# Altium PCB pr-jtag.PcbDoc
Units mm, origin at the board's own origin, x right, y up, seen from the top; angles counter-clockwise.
Board outline 152.4 x 101.6 mm, 2 copper layers (Top Layer, Bottom Layer); 10 components, 21 nets, 69 pads, 6 vias.
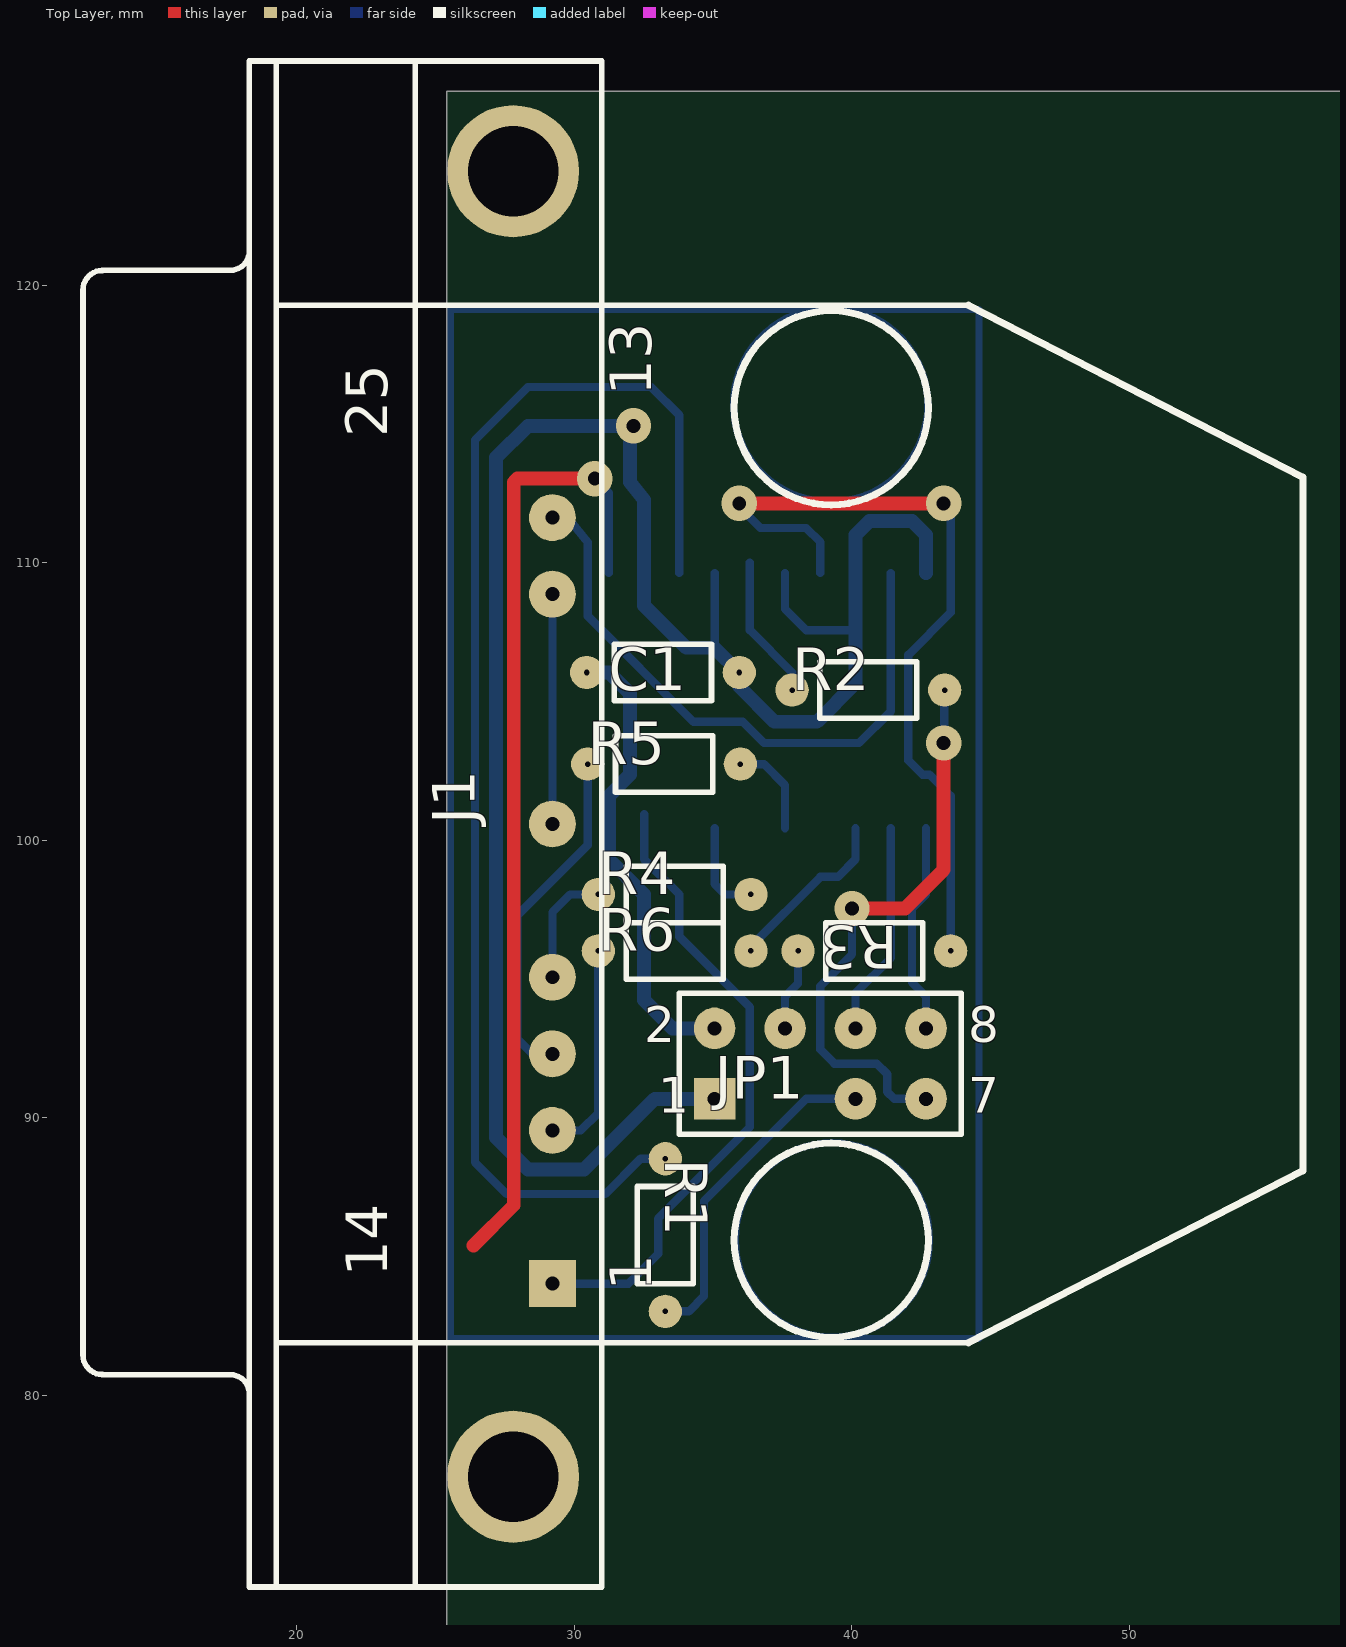
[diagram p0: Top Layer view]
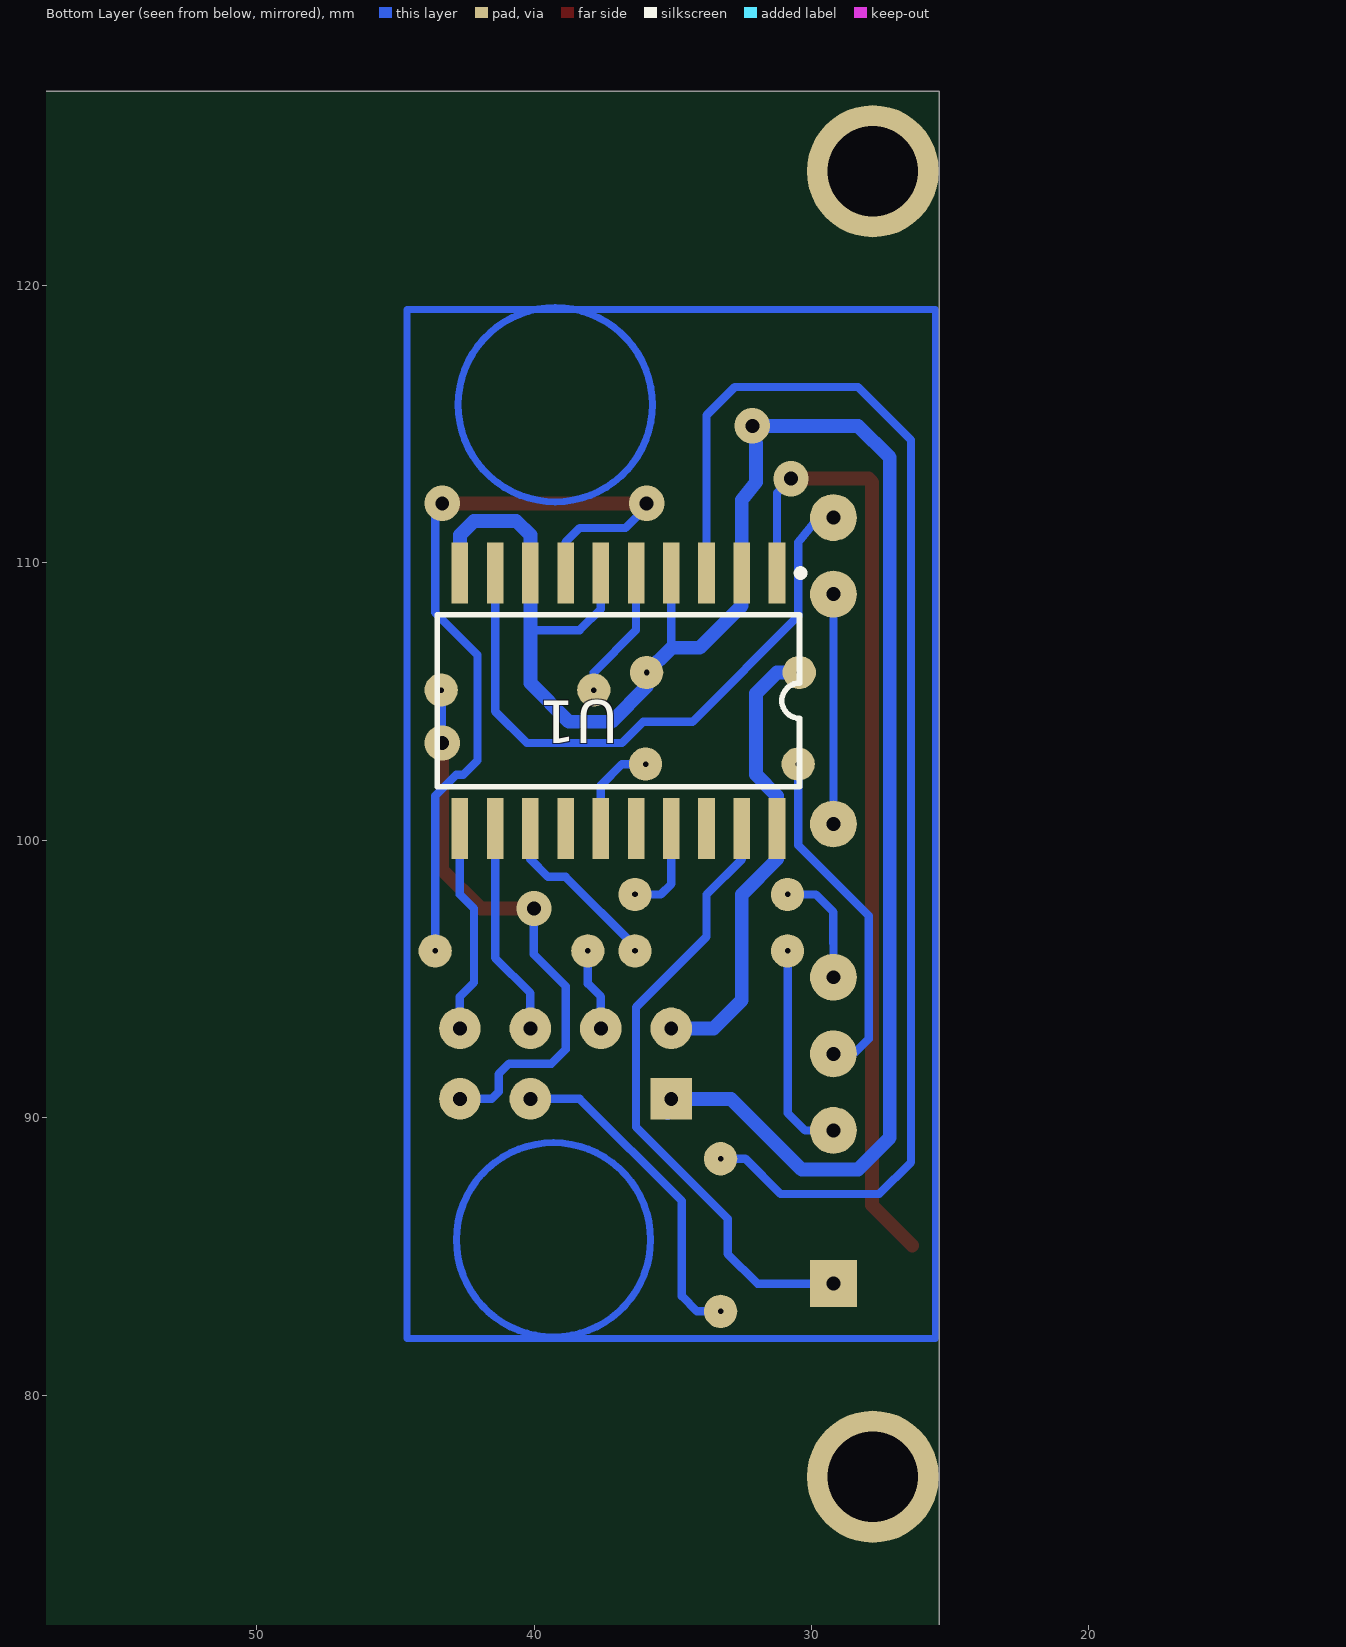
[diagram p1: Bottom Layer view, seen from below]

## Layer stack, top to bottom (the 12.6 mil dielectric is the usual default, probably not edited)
Top Layer: signal copper 0.0356
Dielectric: dielectric 0.32, FR-4, Dk 4.8
Bottom Layer: signal copper 0.0356

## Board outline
25.4,25.4 177.8,25.4 177.8,127 25.4,127

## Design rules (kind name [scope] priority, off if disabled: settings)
Clearance [All] p1: gap=0.254
ComponentClearance [All] p1: gap=0.254 collisioncheckmode=0
PolygonConnect [All] p1: connectstyle=Relief reliefconductorwidth=0.254 reliefentries=4 polygonreliefangle="90 Angle"
RoomDefinition pr-jtag [InComponentClass('pr-jtag')] p1: confinementstyle=ConfineIn formatcopy=TRUE outline 0,0 50.8,0 50.8,25.4 0,25.4
RoutingLayers [All] p1: top layer="Not Used" bottom layer=Vertical
RoutingVias [All] p1: holewidth=0.711 width=1.27 viastyle="Through Hole" minholewidth=0.711 minwidth=1.27 maxholewidth=0.711 maxwidth=1.27
SolderMaskExpansion [All] p1: expansion=0.102
TestPointUsage [All] p1: valid=0 allowmultiple=FALSE
Testpoint [All] p1: side=15 testpointundercomponent=TRUE minsize=1.016 maxsize=2.54 preferedsize=1.524 minholesize=0 maxholesize=1.016 preferedholesize=0.813 testpointgrid=0.025 style=1023 order=1234567890
Width [All] p1: maxlimit=0.5 minlimit=0.254 preferedwidth=0.5 bottomlayer_prefwidth=0.3 minimp=50.000000 maximp=50.000000 favimp=50.000000
16 further rules are at their usual default settings.

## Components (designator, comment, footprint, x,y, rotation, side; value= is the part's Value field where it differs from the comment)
C1 "Cap" "res 5mm" 35.941,106.045 r180 top (schematic designator C?)
J1 "D Connector 25" DB25-tapa 26.416,100.584 r90 top (schematic designator J?)
JP1 "Header 8" HDR2X4 35.052,90.678 r0 top (schematic designator JP?)
R1 "Res1" "Res 5mm" 33.274,88.519 r270 top (schematic designator R?)
R2 "Res1" "Res 5mm" 37.846,105.41 r0 top (schematic designator R?)
R3 "Res1" "Res 5mm" 43.561,96.012 r180 top (schematic designator R?)
R4 "Res1" "Res 5mm" 30.861,98.044 r0 top (schematic designator R?)
R5 "Res1" "Res 5mm" 30.48,102.743 r0 top (schematic designator R?)
R6 "Res1" "Res 5mm" 30.861,96.012 r0 top (schematic designator R?)
U1 "SN74LVC244DB" SO-G20 36.957,105.029 r0 bottom (schematic designator U?)

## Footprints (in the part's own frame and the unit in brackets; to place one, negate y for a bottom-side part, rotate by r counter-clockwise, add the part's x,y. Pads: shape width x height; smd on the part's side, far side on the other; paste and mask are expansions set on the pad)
DB25-tapa [mm]
  rect 1.69x1.69 hole 0.5: 1(-16.566,-2.792)
  round 1.69 on Mech1: 2(-13.805,-2.792) 6(-2.761,-2.792) 8(2.761,-2.792) 9(5.522,-2.792) 12(13.805,-2.792) 13(16.566,-2.792) 14(-15.185,0.048) 15(-12.425,0.048) 16(-9.663,0.048) 17(-6.903,0.048) 18(-4.142,0.048) 19(-1.38,0.048) 20(1.38,0.048) 21(4.142,0.048) 22(6.903,0.048) 23(9.663,0.048) 24(12.425,0.048) 25(15.185,0.048)
  round 1.69 hole 0.5: 3(-11.044,-2.792) 4(-8.283,-2.792) 5(-5.522,-2.792) 7(0,-2.792) 10(8.283,-2.792) 11(11.044,-2.792)
  round 4.76 hole 3.26: 26(-23.526,-1.372) 27(23.526,-1.372)
  silkscreen extent -27.5,-29.84 27.5,14.13
HDR2X4 [mm]
  rect 1.5x1.5 hole 0.5: 1(0,0)
  round 1.5 hole 0.5: 2(0,2.54) 4(2.54,2.54) 5(5.08,0) 6(5.08,2.54) 7(7.62,0) 8(7.62,2.54)
  round 1.5 on Mech1: 3(2.54,0)
  silkscreen extent -1.27,-1.27 8.89,3.81
"res 5mm" [mm]
  round 1.2 hole 0.2: 1(0,0) 2(5.5,0)
  silkscreen extent 1,-1.02 4.5,1.02
"Res 5mm" [mm]
  round 1.2 hole 0.2: 1(0,0) 2(5.5,0)
  silkscreen extent 1,-1.02 4.5,1.02
SO-G20 [mm]
  rect 0.6x2.2 smd: 1(-5.715,-4.6) 2(-4.445,-4.6) 3(-3.175,-4.6) 4(-1.905,-4.6) 5(-0.635,-4.6) 6(0.635,-4.6) 7(1.905,-4.6) 8(3.175,-4.6) 9(4.445,-4.6) 10(5.715,-4.6) 11(5.715,4.6) 12(4.445,4.6) 13(3.175,4.6) 14(1.905,4.6) 15(0.635,4.6) 16(-0.635,4.6) 17(-1.905,4.6) 18(-3.175,4.6) 19(-4.445,4.6) 20(-5.715,4.6)
  silkscreen extent -6.69,-4.72 6.53,3.1

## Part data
C1: "Capacitor"
J1: "Receptacle Assembly, 25 Position, Right Angle"
JP1: "Header, 8-Pin"
R1 R2 R3 R4 R5 R6: "Resistor"
U1: library part DM74LS244N, "Octal 3-State Buffer/Line Driver/Line Receiver"

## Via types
v1: diameter 1.27, hole 0.5, Top Layer to Bottom Layer, 6 vias

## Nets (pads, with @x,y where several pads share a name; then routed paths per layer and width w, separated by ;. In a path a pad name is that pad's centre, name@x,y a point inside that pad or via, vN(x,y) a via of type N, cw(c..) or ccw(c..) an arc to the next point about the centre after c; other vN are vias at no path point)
BUSY: J1.11 U1.9 | length 22.6
  Bottom Layer w0.3: J1.11 29.845,111.506 30.48,110.744 30.48,108.077 34.29,104.267 36.068,104.267 36.83,103.505 40.259,103.505 41.402,104.648 U1.9
GND: C1.1 JP1.1 U1.2 U1.4 U1.6 U1.8 U1.10 | length 73.5
  Bottom Layer w0.3: 35.052,106.934 U1.4 ; U1.6 37.592,108.331 38.354,107.569 40.132,107.569
  Bottom Layer w0.5: JP1.1 32.893,90.678 30.353,88.138 28.321,88.138 27.178,89.281 27.178,113.792 28.321,114.935 v1(32.131,114.935) 32.004,114.3 32.004,112.903 32.512,112.268 32.512,108.458 34.036,106.934 35.052,106.934 C1.1 35.941,105.537 37.211,104.267 38.735,104.267 40.132,105.664 40.132,110.998 40.64,111.506 42.164,111.506 42.672,110.998 U1.10 ; JP1.1@35.052,90.932 35.093,90.685 JP1.1@35.179,90.17
NetJ1_1: J1.1 U1.19 | length 23
  Bottom Layer w0.3: J1.1 31.948,84.018 33.02,85.09 33.02,86.36 36.322,89.662 36.322,93.98 33.782,96.52 33.782,98.044 32.512,99.314 U1.19@32.512,100.937
NetJ1_3: J1.3 R6.1 | length 7.8
  Bottom Layer w0.3: J1.3 30.226,89.535 30.861,90.17 R6.1
NetJ1_4: J1.4 R5.1 | length 12.4
  Bottom Layer w0.3: J1.4 28.448,92.329 27.94,92.837 27.94,97.282 30.48,99.822 R5.1
NetJ1_5: J1.5 R4.1 | length 4.3
  Bottom Layer w0.3: J1.5 29.21,97.409 29.845,98.044 R4.1
NetJ1_7: J1.7 J1.10 | length 8.3
  Bottom Layer w0.3: J1.7 J1.10
NetJ1_14: U1.1 | length 34.7
  Top Layer w0.5: 26.368,85.399 27.813,86.844 27.813,112.903 27.94,113.03 v1(30.734,113.03)
  Bottom Layer w0.3: v1(30.734,113.03) 31.242,112.522 U1.1
NetJ1_18: 
NetR1_1: R1.1 U1.3 | length 48.2
  Bottom Layer w0.3: R1.1 32.385,88.519 31.115,87.249 27.559,87.249 26.416,88.392 26.416,114.427 28.321,116.332 32.766,116.332 33.782,115.316 U1.3
NetR2_1: R2.1 U1.5 | length 5.2
  Bottom Layer w0.3: U1.5@36.322,110.01 36.322,107.569 37.846,106.045 R2.1
NetR3_1: R3.1 U1.7 | length 29.6
  Top Layer w0.5: v1(35.941,112.141) v1(43.307,112.141)
  Bottom Layer w0.3: v1(35.941,112.141) 36.068,111.887 36.703,111.252 38.354,111.252 38.862,110.744 U1.7 ; v1(43.307,112.141) 43.561,111.633 43.561,110.617 43.561,108.204 42.037,106.68 42.037,102.87 42.545,102.362 42.799,102.362 43.561,101.6 43.561,98.552 43.561,97.79 R3.1
NetR4_2: R4.2 U1.17 | length 3.7
  Bottom Layer w0.3: U1.17 35.052,98.425 35.433,98.044 R4.2@36.615,98.044
NetR5_2: R5.2 U1.15 | length 3.5
  Bottom Layer w0.3: R5.2 36.83,102.743 37.592,101.981 U1.15
NetR6_2: R6.2 U1.13 | length 6.4
  Bottom Layer w0.3: R6.2 36.361,96.178 38.862,98.679 39.497,98.679 40.132,99.314 U1.13
NSRST: JP1.6 U1.12 | length 7.7
  Bottom Layer w0.3: JP1.6 40.132,94.488 41.402,95.758 U1.12
TCK: JP1.7 R2.2 | length 21.6
  Top Layer w0.5: v1(40.005,97.536) 41.91,97.536 43.307,98.933 v1(43.307,103.505)
  Bottom Layer w0.3: v1@40.005,97.663 40.005,95.885 38.862,94.742 38.862,92.456 39.37,91.948 40.894,91.948 41.275,91.567 41.275,90.932 41.529,90.678 JP1.7 ; JP1.7@42.672,90.17 JP1.7@42.672,90.805 ; v1(43.307,103.505) R2.2
TDI: JP1.5 R1.2 | length 12.4
  Bottom Layer w0.3: R1.2 34.124,83.019 34.671,83.566 34.671,86.995 38.354,90.678 JP1.5 ; JP1.5@39.878,90.678 JP1.5@40.132,90.932
TDO: JP1.8 U1.11 | length 7.6
  Bottom Layer w0.3: JP1.8 42.672,94.361 42.164,94.869 42.164,97.536 42.672,98.044 U1.11
TMS: JP1.4 R3.2 | length 2.7
  Bottom Layer w0.3: JP1.4 37.592,94.361 38.061,94.83 R3.2@38.061,95.758
VCC: C1.2 JP1.2 U1.20 | length 16.7
  Bottom Layer w0.5: C1.2 31.242,106.045 32.004,105.283 32.004,102.362 31.242,101.6 U1.20 31.242,99.314 32.512,98.044 32.512,94.234 33.528,93.218 JP1.2
pads on no net: J1.2 J1.6 J1.8 J1.9 J1.12 J1.13 J1.14 J1.15 J1.16 J1.17 J1.18 J1.19 J1.20 J1.21 J1.22 J1.23 J1.24 J1.25 J1.26 J1.27 JP1.3 U1.14 U1.16 U1.18
copper on no net: | length 156.3
  Bottom Layer w0.254: 25.527,82.042 44.577,82.042 44.577,119.126 25.527,119.126 25.527,82.042 ; 42.734,115.697 ccw(c39.234,115.697) 42.734,115.697 ; 42.799,85.598 ccw(c39.299,85.598) 42.799,85.598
